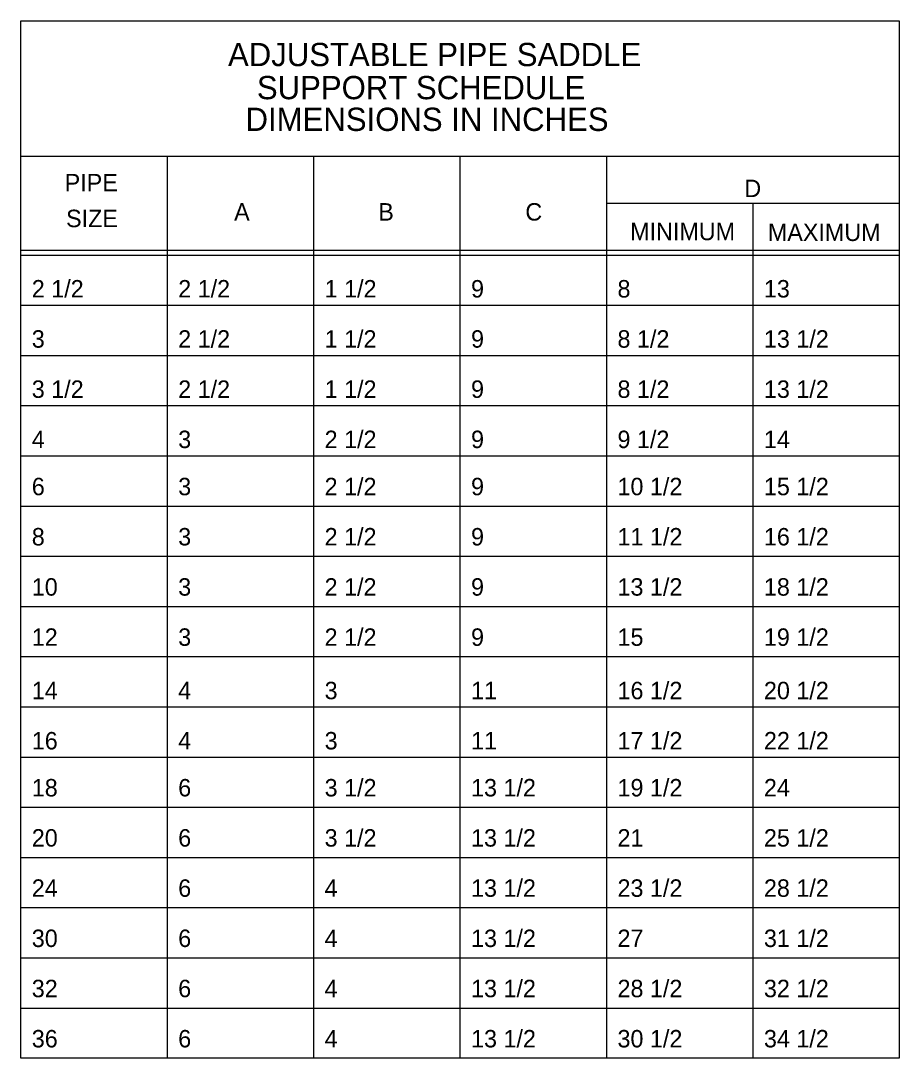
# Model space of a CAD drawing. Extents: x -123486 to -116575, y -107066 to -101122.
# Drawn here: x -116877.3 to -116575.2, y -102063.3 to -101706.4 of the extents above; entities that cross this region are included whole.
import ezdxf

# ---------------------------------------------------------------- set-up
doc = ezdxf.new("R2010")
doc.units = 0
doc.layers.add('Misc CnstDet(22)', color=7, linetype='Continuous')

msp = doc.modelspace()

# ---------------------------------------------------------------- linework, layer by layer
at = {"layer": 'Misc CnstDet(22)'}
for p, q in [((-116877.27, -101706.44), (-116575.19, -101706.44)), ((-116877.27, -102063.35), (-116877.27, -101706.44)), ((-116575.19, -101706.44), (-116575.19, -102063.35)), ((-116877.27, -101753.04), (-116575.19, -101753.04)), ((-116826.92, -101753.04), (-116826.92, -102063.35)), ((-116776.58, -101753.04), (-116776.58, -102063.35)), ((-116726.23, -101753.04), (-116726.23, -102063.35)), ((-116675.88, -101753.04), (-116675.88, -102063.35)), ((-116675.88, -101769.21), (-116575.19, -101769.21)), ((-116625.53, -101769.21), (-116625.53, -102063.35)), ((-116877.27, -101785.38), (-116575.19, -101785.38)), ((-116877.27, -101787.03), (-116575.19, -101787.03)), ((-116877.27, -101804.3), (-116575.19, -101804.3)), ((-116877.27, -101821.57), (-116575.19, -101821.57)), ((-116877.27, -101838.84), (-116575.19, -101838.84)), ((-116877.27, -101856.11), (-116575.19, -101856.11)), ((-116877.27, -101873.38), (-116575.19, -101873.38)), ((-116877.27, -101890.65), (-116575.19, -101890.65)), ((-116877.27, -101907.92), (-116575.19, -101907.92)), ((-116877.27, -101925.19), (-116575.19, -101925.19)), ((-116877.27, -101942.46), (-116575.19, -101942.46)), ((-116877.27, -101959.73), (-116575.19, -101959.73)), ((-116877.27, -101977), (-116575.19, -101977)), ((-116877.27, -101994.27), (-116575.19, -101994.27)), ((-116877.27, -102011.54), (-116575.19, -102011.54)), ((-116877.27, -102028.81), (-116575.19, -102028.81)), ((-116877.27, -102046.08), (-116575.19, -102046.08)), ((-116575.19, -102063.35), (-116877.27, -102063.35))]:
    msp.add_line(p, q, dxfattribs=at)

# ---------------------------------------------------------------- texts
for s, height, p in [('ADJUSTABLE PIPE SADDLE', 8, (-116806, -101722.05)), ('SUPPORT SCHEDULE', 8, (-116796.07, -101733.43)), ('DIMENSIONS IN INCHES', 8, (-116799.96, -101744.34)), ('PIPE', 6, (-116862.17, -101765.13)), ('D', 6, (-116628.46, -101767.1)), ('A', 6, (-116803.9, -101775.18)), ('B', 6, (-116754.33, -101775.18)), ('C', 6, (-116703.76, -101775.18)), ('SIZE', 6, (-116861.69, -101777.44)), ('MINIMUM', 6, (-116667.74, -101781.93)), ('MAXIMUM', 6, (-116620.36, -101782.2)), ('2 1/2', 6, (-116873.48, -101801.64)), ('2 1/2', 6, (-116823.13, -101801.64)), ('1 1/2', 6, (-116772.78, -101801.64)), ('9', 6, (-116722.43, -101801.64)), ('8', 6, (-116672.07, -101801.64)), ('13', 6, (-116621.72, -101801.64)), ('3', 6, (-116873.48, -101818.9)), ('2 1/2', 6, (-116823.13, -101818.9)), ('1 1/2', 6, (-116772.78, -101818.9)), ('9', 6, (-116722.43, -101818.9)), ('8 1/2', 6, (-116672.07, -101818.9)), ('13 1/2', 6, (-116621.72, -101818.9)), ('3 1/2', 6, (-116873.48, -101836.17)), ('2 1/2', 6, (-116823.13, -101836.17)), ('1 1/2', 6, (-116772.78, -101836.17)), ('9', 6, (-116722.43, -101836.17)), ('8 1/2', 6, (-116672.07, -101836.17)), ('13 1/2', 6, (-116621.72, -101836.17)), ('4', 6, (-116873.48, -101853.44)), ('3', 6, (-116823.13, -101853.44)), ('2 1/2', 6, (-116772.78, -101853.44)), ('9', 6, (-116722.43, -101853.44)), ('9 1/2', 6, (-116672.07, -101853.44)), ('14', 6, (-116621.72, -101853.44)), ('6', 6, (-116873.48, -101869.67)), ('3', 6, (-116823.13, -101869.67)), ('2 1/2', 6, (-116772.78, -101869.67)), ('9', 6, (-116722.43, -101869.67)), ('10 1/2', 6, (-116672.07, -101869.67)), ('15 1/2', 6, (-116621.72, -101869.67)), ('8', 6, (-116873.48, -101886.94)), ('3', 6, (-116823.13, -101886.94)), ('2 1/2', 6, (-116772.78, -101886.94)), ('9', 6, (-116722.43, -101886.94)), ('11 1/2', 6, (-116672.07, -101886.94)), ('16 1/2', 6, (-116621.72, -101886.94)), ('2 1/2', 6, (-116772.78, -101904.21)), ('13 1/2', 6, (-116672.07, -101904.21)), ('18 1/2', 6, (-116621.72, -101904.21)), ('10', 6, (-116873.48, -101904.21)), ('3', 6, (-116823.13, -101904.21)), ('9', 6, (-116722.43, -101904.21)), ('12', 6, (-116873.48, -101921.47)), ('3', 6, (-116823.13, -101921.47)), ('2 1/2', 6, (-116772.78, -101921.47)), ('9', 6, (-116722.43, -101921.47)), ('15', 6, (-116672.07, -101921.47)), ('19 1/2', 6, (-116621.72, -101921.47)), ('16 1/2', 6, (-116672.07, -101939.85)), ('20 1/2', 6, (-116621.72, -101939.85)), ('14', 6, (-116873.48, -101939.85)), ('4', 6, (-116823.13, -101939.85)), ('3', 6, (-116772.78, -101939.85)), ('11', 6, (-116722.43, -101939.85)), ('16', 6, (-116873.48, -101957.11)), ('4', 6, (-116823.13, -101957.11)), ('3', 6, (-116772.78, -101957.11)), ('11', 6, (-116722.43, -101957.11)), ('17 1/2', 6, (-116672.07, -101957.11)), ('22 1/2', 6, (-116621.72, -101957.11)), ('18', 6, (-116873.48, -101973.28)), ('6', 6, (-116823.13, -101973.28)), ('3 1/2', 6, (-116772.78, -101973.28)), ('13 1/2', 6, (-116722.43, -101973.28)), ('19 1/2', 6, (-116672.07, -101973.28)), ('24', 6, (-116621.72, -101973.28)), ('20', 6, (-116873.48, -101990.54)), ('6', 6, (-116823.13, -101990.54)), ('3 1/2', 6, (-116772.78, -101990.54)), ('13 1/2', 6, (-116722.43, -101990.54)), ('21', 6, (-116672.07, -101990.54)), ('25 1/2', 6, (-116621.72, -101990.54)), ('24', 6, (-116873.48, -102007.81)), ('6', 6, (-116823.13, -102007.81)), ('4', 6, (-116772.78, -102007.81)), ('13 1/2', 6, (-116722.43, -102007.81)), ('23 1/2', 6, (-116672.07, -102007.81)), ('28 1/2', 6, (-116621.72, -102007.81)), ('30', 6, (-116873.48, -102025.08)), ('6', 6, (-116823.13, -102025.08)), ('4', 6, (-116772.78, -102025.08)), ('13 1/2', 6, (-116722.43, -102025.08)), ('27', 6, (-116672.07, -102025.08)), ('31 1/2', 6, (-116621.72, -102025.08)), ('32', 6, (-116873.48, -102042.35)), ('6', 6, (-116823.13, -102042.35)), ('4', 6, (-116772.78, -102042.35)), ('13 1/2', 6, (-116722.43, -102042.35)), ('28 1/2', 6, (-116672.07, -102042.35)), ('32 1/2', 6, (-116621.72, -102042.35)), ('36', 6, (-116873.48, -102059.62)), ('6', 6, (-116823.13, -102059.62)), ('4', 6, (-116772.78, -102059.62)), ('13 1/2', 6, (-116722.43, -102059.62)), ('30 1/2', 6, (-116672.07, -102059.62)), ('34 1/2', 6, (-116621.72, -102059.62))]:
    msp.add_text(s, height=height, dxfattribs=at).set_placement(p)

doc.saveas('drawing.dxf')
